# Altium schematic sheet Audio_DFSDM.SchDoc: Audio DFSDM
size A4; Date: Not used; ApprovedBy: Not used; CheckedBy: Not used; Author: Not used; CompanyName: STMicroelectronics; DrawnBy: Not used; Engineer: Not used; Organization: Not used; Address1: Not used; Address2: Not used; Address3: Not used; Address4: Not used; DocumentNumber: Not used; Revision: Not used; SheetNumber: 11; SheetTotal: 23
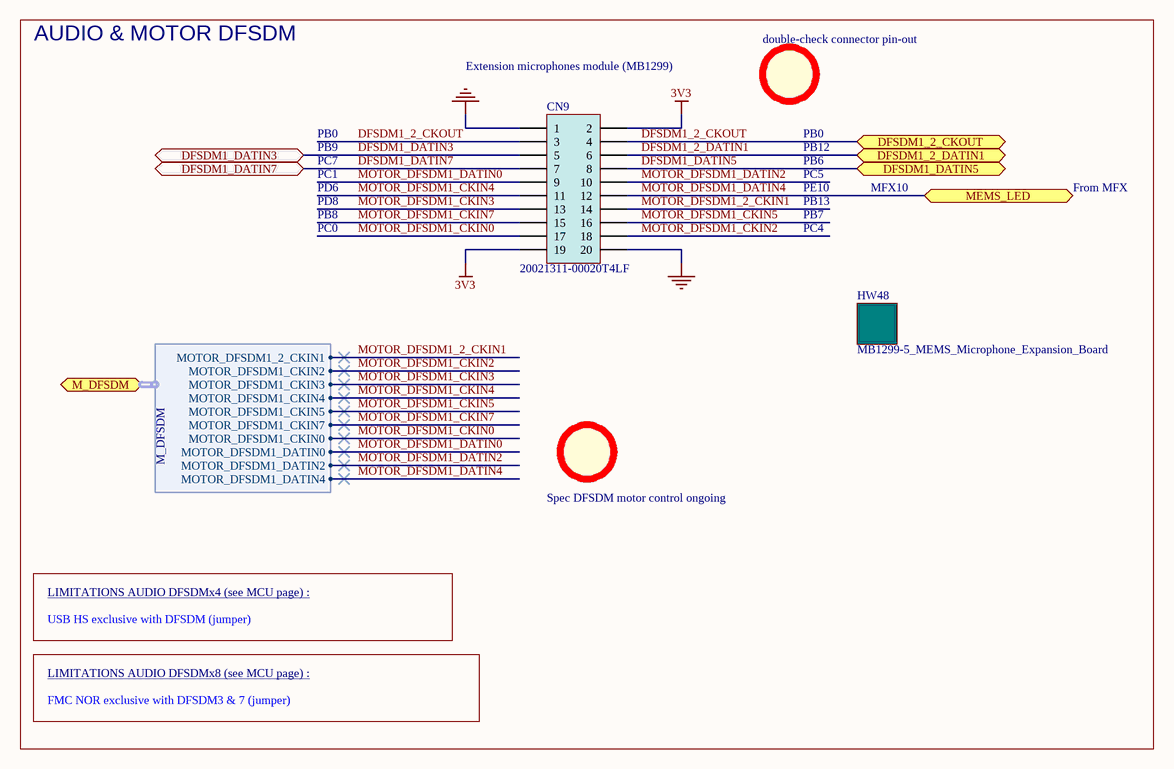
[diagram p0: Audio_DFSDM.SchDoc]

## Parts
CN9  value 20021311-00020T4LF  [CON_FCI_20021311-XXX20XXLF]
HW48  value MB1299-5_MEMS_Microphone_Expansion_Board  [MOD_MB1299_5-MEMS_MICROPHONE-EXPANSION-BOARD]

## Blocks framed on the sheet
AUDIO & MOTOR DFSDM: CN9 HW48

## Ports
DFSDM1_2_CKOUT, DFSDM1_2_DATIN1, DFSDM1_DATIN3, DFSDM1_DATIN5, DFSDM1_DATIN7, M_DFSDM (harness M_DFSDM), MEMS_LED

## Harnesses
M_DFSDM: MOTOR_DFSDM1_2_CKIN1, MOTOR_DFSDM1_CKIN3, MOTOR_DFSDM1_CKIN5, MOTOR_DFSDM1_CKIN7, MOTOR_DFSDM1_CKIN2, MOTOR_DFSDM1_CKIN4, MOTOR_DFSDM1_CKIN0, MOTOR_DFSDM1_DATIN0, MOTOR_DFSDM1_DATIN2, MOTOR_DFSDM1_DATIN4

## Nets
3V3: CN9.2 CN9.19
GND: CN9.1 CN9.20
DFSDM1_2_CKOUT: CN9.3 CN9.4 ; port DFSDM1_2_CKOUT
DFSDM1_2_DATIN1: CN9.6 ; port DFSDM1_2_DATIN1
DFSDM1_DATIN3: CN9.5 ; port DFSDM1_DATIN3
DFSDM1_DATIN5: CN9.8 ; port DFSDM1_DATIN5
DFSDM1_DATIN7: CN9.7 ; port DFSDM1_DATIN7
MOTOR_DFSDM1_2_CKIN1: CN9.14 ; port M_DFSDM.MOTOR_DFSDM1_2_CKIN1
MOTOR_DFSDM1_CKIN0: CN9.17 ; port M_DFSDM.MOTOR_DFSDM1_CKIN0
MOTOR_DFSDM1_CKIN2: CN9.18 ; port M_DFSDM.MOTOR_DFSDM1_CKIN2
MOTOR_DFSDM1_CKIN3: CN9.13 ; port M_DFSDM.MOTOR_DFSDM1_CKIN3
MOTOR_DFSDM1_CKIN4: CN9.11 ; port M_DFSDM.MOTOR_DFSDM1_CKIN4
MOTOR_DFSDM1_CKIN5: CN9.16 ; port M_DFSDM.MOTOR_DFSDM1_CKIN5
MOTOR_DFSDM1_CKIN7: CN9.15 ; port M_DFSDM.MOTOR_DFSDM1_CKIN7
MOTOR_DFSDM1_DATIN0: CN9.9 ; port M_DFSDM.MOTOR_DFSDM1_DATIN0
MOTOR_DFSDM1_DATIN2: CN9.10 ; port M_DFSDM.MOTOR_DFSDM1_DATIN2
MOTOR_DFSDM1_DATIN4: CN9.12 ; port MEMS_LED, port M_DFSDM.MOTOR_DFSDM1_DATIN4

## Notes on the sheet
- double-check connector pin-out
- Extension microphones module (MB1299)
- PB0
- PB9
- PC7
- PC1
- PB12
- PB6
- PC5
- PD8
- PB8
- PC0
- PD6
- PB13
- PB7
- PC4
- PE10
- MFX10
- From MFX
- Spec DFSDM motor control ongoing
- USB HS exclusive with DFSDM (jumper)
- LIMITATIONS AUDIO DFSDMx4 (see MCU page) :
- LIMITATIONS AUDIO DFSDMx8 (see MCU page) :
- FMC NOR exclusive with DFSDM3 & 7 (jumper)

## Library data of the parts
CN9 = MCD-00147: Socket, 10x2, 1.27mm, VR, TH, Height 4.30mm/2.40mm; Manufacturer: FCI; Part_Type: Connector; Provided_By: Subcon; ECCN_US: EAR99; ECCN_EU: NEC; Initial_Board_Reference: MB1262
HW48 = MCD-01031: MB1299 : Expansion Board with 5 x MEMS Microphones; Part_Type: Misc; Manufacturer_Part_Number: MB1299 - 5 x MEMS Microphones Expansion Board; Manufacturer: STMICROELECTRONICS; Provided_By: STM; Initial_Board_Reference: MB1274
